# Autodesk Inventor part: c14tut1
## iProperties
Shininess: 77.0
Angle Display Precision: 2
Document Length Units: 11269
Document Angle Units: 11279
Document Time Units: 11290
Document Mass Units: 11283
Document Length Units Precision: 3
Document Angle Units Precision: 2
Created: 2002-04
Part Number: c14tut1
Document SubType Name: Sheet Metal
Density: 0.0
Volumn: 0.0
Area: 0.0
PropertySet Name: Model Information
Control State: 0
Master: False
Checked Out: False
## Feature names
1. Corner Round1
2. Corner Round2
3. Hole1
4. Hole2
5. Plate1
6. Plate7
7. Bend6
8. Plate10
9. Bend9
10. Plate11
11. Bend10
12. Plate12
13. Bend11
14. Plate13
15. Bend12
16. FlatPatternExtrusion1
17. Cut1
